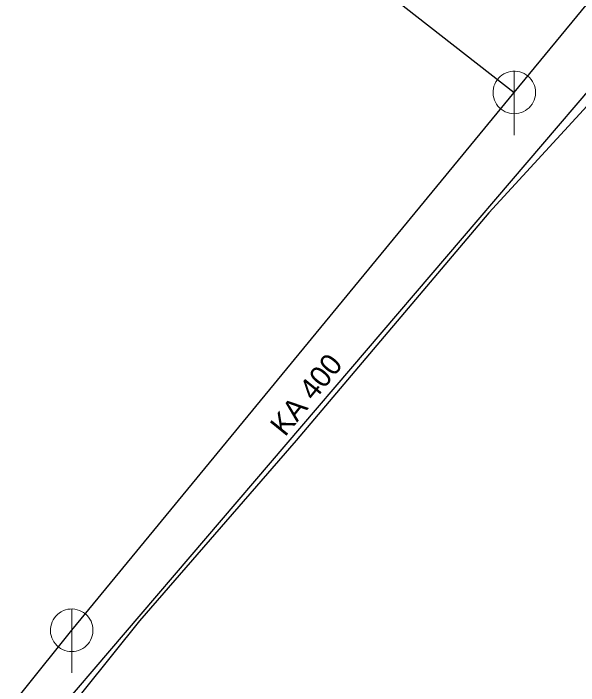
# Model space of a CAD drawing. Extents: x -790267 to -789874, y -989766 to -989454.
# Drawn here: x -789961.05 to -789934.49, y -989637.95 to -989606.39 of the extents above; entities that cross this region are included whole.
import ezdxf

# ---------------------------------------------------------------- set-up
doc = ezdxf.new("R2010")
doc.units = 0
doc.header["$LTSCALE"] = 0.4
doc.layers.add('1', color=7, linetype='Continuous')
for name, color, linetype, lineweight in [('14', 7, 'Continuous', 13), ('17', 7, 'Continuous', 25), ('22', 7, 'Continuous', 13)]:
    doc.layers.add(name, color=color, linetype=linetype, lineweight=lineweight)

msp = doc.modelspace()

# ---------------------------------------------------------------- linework, layer by layer
at = {"layer": '14', "lineweight": 25}
for p, q in [((-789937.51, -989610.1), (-789900.16, -989564.68)), ((-789965.811, -989588.026), (-789937.51, -989610.1))]:
    msp.add_line(p, q, dxfattribs=at)
msp.add_lwpolyline([(-789971.89, -989652.27), (-789958.315, -989635.357), (-789937.51, -989610.1)], dxfattribs=at)
at = {"layer": '17'}
for points in [[(-789931.949, -989608.42), (-789938.71, -989615.75), (-789947.76, -989626.449), (-789955.129, -989634.916), (-789973.42, -989657.67)], [(-789984.21, -989668.683), (-789974.678, -989657.539), (-789933.135, -989608.969)]]:
    msp.add_lwpolyline(points, dxfattribs=at)
at = {"layer": '22'}
for p, q in [((-789937.51, -989612.1), (-789937.509, -989609.1)), ((-789958.315, -989637.357), (-789958.314, -989634.357))]:
    msp.add_line(p, q, dxfattribs=at)
for points in [[(-789936.51, -989610.1), (-789936.515, -989609.991), (-789936.533, -989609.883), (-789936.563, -989609.777), (-789936.603, -989609.676), (-789936.655, -989609.579), (-789936.717, -989609.489), (-789936.789, -989609.406), (-789936.869, -989609.332), (-789936.957, -989609.266), (-789937.051, -989609.211), (-789937.151, -989609.166), (-789937.256, -989609.133), (-789937.363, -989609.111), (-789937.472, -989609.101), (-789937.582, -989609.103), (-789937.69, -989609.117), (-789937.797, -989609.142), (-789937.9, -989609.179), (-789937.998, -989609.228), (-789938.09, -989609.286), (-789938.176, -989609.355), (-789938.253, -989609.432), (-789938.322, -989609.518), (-789938.381, -989609.61), (-789938.429, -989609.708), (-789938.466, -989609.811), (-789938.492, -989609.918), (-789938.506, -989610.026), (-789938.509, -989610.136), (-789938.499, -989610.245), (-789938.478, -989610.352), (-789938.444, -989610.456), (-789938.4, -989610.556), (-789938.345, -989610.651), (-789938.279, -989610.739), (-789938.205, -989610.819), (-789938.122, -989610.891), (-789938.032, -989610.953), (-789937.936, -989611.005), (-789937.834, -989611.046), (-789937.729, -989611.076), (-789937.621, -989611.094), (-789937.511, -989611.1), (-789937.402, -989611.094), (-789937.294, -989611.076), (-789937.189, -989611.047), (-789937.087, -989611.006), (-789936.99, -989610.954), (-789936.9, -989610.892), (-789936.817, -989610.821), (-789936.742, -989610.741), (-789936.677, -989610.653), (-789936.621, -989610.559), (-789936.577, -989610.459), (-789936.543, -989610.355), (-789936.521, -989610.247), (-789936.511, -989610.138)], [(-789957.315, -989635.357), (-789957.32, -989635.248), (-789957.338, -989635.14), (-789957.368, -989635.034), (-789957.408, -989634.933), (-789957.46, -989634.836), (-789957.522, -989634.746), (-789957.594, -989634.663), (-789957.674, -989634.589), (-789957.762, -989634.523), (-789957.856, -989634.468), (-789957.956, -989634.423), (-789958.061, -989634.39), (-789958.168, -989634.368), (-789958.277, -989634.358), (-789958.387, -989634.36), (-789958.495, -989634.374), (-789958.602, -989634.399), (-789958.705, -989634.436), (-789958.803, -989634.485), (-789958.895, -989634.543), (-789958.981, -989634.612), (-789959.058, -989634.689), (-789959.127, -989634.775), (-789959.186, -989634.867), (-789959.234, -989634.965), (-789959.271, -989635.068), (-789959.297, -989635.175), (-789959.311, -989635.283), (-789959.314, -989635.393), (-789959.304, -989635.502), (-789959.283, -989635.609), (-789959.249, -989635.713), (-789959.205, -989635.813), (-789959.15, -989635.908), (-789959.084, -989635.996), (-789959.01, -989636.076), (-789958.927, -989636.148), (-789958.837, -989636.21), (-789958.741, -989636.262), (-789958.639, -989636.303), (-789958.534, -989636.333), (-789958.426, -989636.351), (-789958.316, -989636.357), (-789958.207, -989636.351), (-789958.099, -989636.333), (-789957.994, -989636.304), (-789957.892, -989636.263), (-789957.795, -989636.211), (-789957.705, -989636.149), (-789957.622, -989636.078), (-789957.547, -989635.998), (-789957.482, -989635.91), (-789957.426, -989635.816), (-789957.382, -989635.716), (-789957.348, -989635.612), (-789957.326, -989635.504), (-789957.316, -989635.395)]]:
    msp.add_lwpolyline(points, close=True, dxfattribs=at)

# ---------------------------------------------------------------- texts
at = {"layer": '1'}
msp.add_text('KA 400', height=1, rotation=51, dxfattribs=at).set_placement((-789948.287, -989626.305))

doc.saveas('drawing.dxf')
